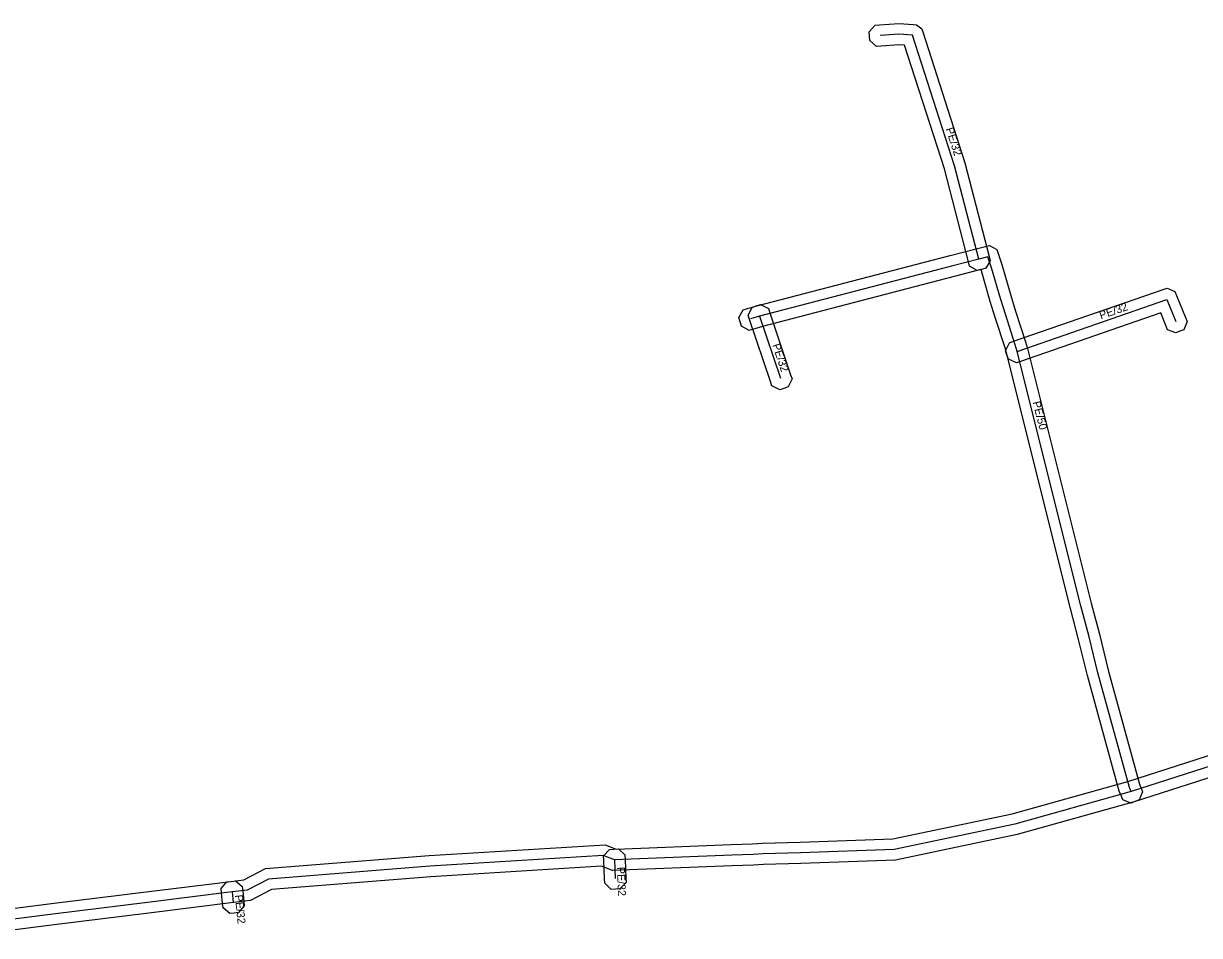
# Model space of a CAD drawing. Extents: x -682697 to -681888, y -1059966 to -1059631.
# Drawn here: x -682493.5 to -682383.3, y -1059851.7 to -1059766.2 of the extents above; entities that cross this region are included whole.
import ezdxf

# ---------------------------------------------------------------- set-up
doc = ezdxf.new("R2010")
doc.units = 0
for name, color, linetype in [('1', 7, 'Continuous'), ('24', 7, 'Continuous'), ('30', 7, 'Continuous')]:
    doc.layers.add(name, color=color, linetype=linetype)

msp = doc.modelspace()

# ---------------------------------------------------------------- linework, layer by layer
at = {"layer": '1'}
for points in [[(-682404.81, -1059788.98), (-682404.92, -1059788.58), (-682407.17, -1059779.86), (-682410.9, -1059768.29), (-682411.44, -1059768.25), (-682413.11, -1059768.37), (-682413.52, -1059768.4), (-682414.15, -1059767.85), (-682414.18, -1059767.44), (-682414.21, -1059767.03), (-682413.66, -1059766.4), (-682413.25, -1059766.37), (-682411.44, -1059766.25), (-682410.08, -1059766.34), (-682409.77, -1059766.36), (-682409.29, -1059766.74), (-682409.2, -1059767.03), (-682405.25, -1059779.3), (-682402.98, -1059788.08), (-682402.88, -1059788.48), (-682403.3, -1059789.19), (-682403.7, -1059789.3), (-682404.1, -1059789.4)], [(-682403.7, -1059789.44), (-682403.75, -1059789.31), (-682406.12, -1059789.93), (-682408.54, -1059790.56), (-682424.21, -1059794.63), (-682424.83, -1059794.82), (-682425.07, -1059794.89), (-682425.47, -1059795.01), (-682426.19, -1059794.61), (-682426.31, -1059794.21), (-682426.43, -1059793.81), (-682426.03, -1059793.09), (-682425.63, -1059792.97), (-682425.39, -1059792.9), (-682424.75, -1059792.71), (-682409.04, -1059788.62), (-682406.62, -1059787.99), (-682404.2, -1059787.36), (-682403.33, -1059787.15), (-682402.95, -1059787.06), (-682402.27, -1059787.43), (-682402.14, -1059787.8), (-682401.8, -1059788.84), (-682400.96, -1059791.73), (-682400.51, -1059793.2), (-682399.57, -1059796.07), (-682399.39, -1059796.71), (-682393.41, -1059820.57), (-682392.65, -1059823.47), (-682391.82, -1059826.84), (-682388.88, -1059837.54), (-682388.75, -1059837.85), (-682388.6, -1059838.24), (-682388.92, -1059839), (-682389.3, -1059839.16), (-682389.69, -1059839.31), (-682390.45, -1059838.99), (-682390.61, -1059838.61), (-682390.78, -1059838.18), (-682393.76, -1059827.34), (-682394.59, -1059823.97), (-682395.35, -1059821.07), (-682401.33, -1059797.23), (-682401.49, -1059796.65), (-682402.41, -1059793.8), (-682402.88, -1059792.31)], [(-682401.08, -1059796.16), (-682400.69, -1059796.02), (-682386.67, -1059791.18), (-682386.29, -1059791.04), (-682385.57, -1059791.37), (-682385.42, -1059791.74), (-682384.57, -1059793.79), (-682384.41, -1059794.17), (-682384.72, -1059794.94), (-682385.11, -1059795.09), (-682385.49, -1059795.25), (-682386.26, -1059794.94), (-682386.41, -1059794.55), (-682386.9, -1059793.37), (-682400.03, -1059797.92), (-682400.42, -1059798.05), (-682401.17, -1059797.69), (-682401.31, -1059797.3), (-682401.44, -1059796.91)], [(-682423.66, -1059792.96), (-682423.53, -1059793.35), (-682421.58, -1059799.17), (-682421.45, -1059799.56), (-682421.82, -1059800.31), (-682422.21, -1059800.44), (-682422.6, -1059800.57), (-682423.35, -1059800.2), (-682423.48, -1059799.81), (-682425.43, -1059793.99), (-682425.56, -1059793.59), (-682425.19, -1059792.85), (-682424.8, -1059792.72), (-682424.41, -1059792.59)], [(-682437.11, -1059844.17), (-682437.09, -1059844.58), (-682437.02, -1059846.33), (-682437, -1059846.74), (-682437.57, -1059847.35), (-682437.98, -1059847.37), (-682438.39, -1059847.39), (-682439, -1059846.82), (-682439.02, -1059846.41), (-682439.09, -1059844.66), (-682439.11, -1059844.25), (-682438.54, -1059843.64), (-682438.13, -1059843.62), (-682437.72, -1059843.6)], [(-682472.96, -1059847.12), (-682472.92, -1059847.53), (-682472.82, -1059848.52), (-682472.77, -1059848.93), (-682473.3, -1059849.57), (-682473.71, -1059849.61), (-682474.12, -1059849.66), (-682474.76, -1059849.13), (-682474.81, -1059848.72), (-682474.91, -1059847.73), (-682474.95, -1059847.32), (-682474.42, -1059846.68), (-682474.01, -1059846.64), (-682473.6, -1059846.59)]]:
    msp.add_lwpolyline(points, close=True, dxfattribs=at)
for points in [[(-682498.7, -1059849.73), (-682490.83, -1059848.73), (-682481.97, -1059847.63), (-682474.03, -1059846.64), (-682472.8, -1059846.5), (-682470.79, -1059845.45), (-682455.44, -1059844.22), (-682438.97, -1059843.21), (-682437.92, -1059843.61), (-682427.14, -1059843.19), (-682425.14, -1059843.11), (-682424.21, -1059843.07), (-682420.68, -1059842.96), (-682412, -1059842.64), (-682400.82, -1059840.32), (-682389.97, -1059837.27), (-682380.78, -1059834.33)], [(-682380.04, -1059836.19), (-682389.39, -1059839.19), (-682400.34, -1059842.26), (-682411.76, -1059844.64), (-682420.62, -1059844.96), (-682424.13, -1059845.07), (-682425.06, -1059845.11), (-682427.06, -1059845.19), (-682438.26, -1059845.63), (-682439.29, -1059845.23), (-682455.3, -1059846.22), (-682470.23, -1059847.41), (-682472.2, -1059848.44), (-682473.79, -1059848.62), (-682481.73, -1059849.61), (-682490.58, -1059850.71), (-682498.45, -1059851.71)]]:
    msp.add_lwpolyline(points, dxfattribs=at)
at = {"layer": '24'}
for points in [[(-682403.95, -1059788.33), (-682406.21, -1059779.58), (-682410.15, -1059767.34), (-682411.44, -1059767.25), (-682413.18, -1059767.37)], [(-682389.68, -1059838.23), (-682389.83, -1059837.86), (-682392.79, -1059827.09), (-682393.62, -1059823.72), (-682394.38, -1059820.82), (-682400.36, -1059796.97), (-682400.53, -1059796.36), (-682401.46, -1059793.5), (-682401.92, -1059792.02), (-682402.75, -1059789.14), (-682403.09, -1059788.12), (-682403.95, -1059788.33), (-682406.37, -1059788.96), (-682408.79, -1059789.59), (-682424.48, -1059793.67), (-682425.11, -1059793.86), (-682425.35, -1059793.93)], [(-682400.36, -1059796.97), (-682386.34, -1059792.12), (-682385.49, -1059794.17)], [(-682424.48, -1059793.67), (-682422.53, -1059799.49)], [(-682380.41, -1059835.26), (-682389.68, -1059838.23), (-682400.58, -1059841.29), (-682411.88, -1059843.64), (-682420.65, -1059843.96), (-682424.17, -1059844.07), (-682425.1, -1059844.11), (-682427.1, -1059844.19), (-682438.09, -1059844.62), (-682439.13, -1059844.22), (-682455.37, -1059845.22), (-682470.51, -1059846.43), (-682472.5, -1059847.47), (-682473.91, -1059847.63), (-682481.85, -1059848.62), (-682490.7, -1059849.72), (-682498.58, -1059850.72)], [(-682438.09, -1059844.62), (-682438.02, -1059846.37)], [(-682473.91, -1059847.63), (-682473.81, -1059848.62)]]:
    msp.add_lwpolyline(points, dxfattribs=at)

# ---------------------------------------------------------------- texts
at = {"layer": '30'}
for s, rotation, p in [('PE/32', 287.8431, (-682407.06, -1059776.12)), ('PE/32', 19.0823, (-682392.5, -1059793.98)), ('PE/32', 288.5235, (-682423.31, -1059796.38)), ('PE/50', 284.0758, (-682398.91, -1059801.74)), ('PE/32', 272.2906, (-682437.86, -1059845.3)), ('PE/32', 275.7679, (-682473.66, -1059847.93))]:
    msp.add_text(s, height=0.75, rotation=rotation, dxfattribs=at).set_placement(p)

doc.saveas('drawing.dxf')
